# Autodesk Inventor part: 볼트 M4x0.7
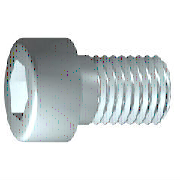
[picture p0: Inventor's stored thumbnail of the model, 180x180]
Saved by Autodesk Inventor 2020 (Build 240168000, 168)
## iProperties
IsCustomPart: 1
Created: 2015-10
Part Number: 볼트 M4x0.7
Material: 스테인리스강
Description: 6각머리 태핑 나사
Document SubType Name: Modeling
Standard: KS B 1003
Designer: mdu
Standards Organization: KS
Language: ko-KR
Size Designation: M 4 x 16
Categories: <MemberInstance><Categories><Category DisplayName="조임쇠" InternalName="e4da775c-781d-43d5-af7c-5136215cf5a6" Mnemonic="FSTN"><Category DisplayName="볼트" InternalN
Density: 8.08 g/cm^3
Mass: 2.70334 g
Surface Area: 3.81118 cm^2
Volume: 0.334572 cm^3
Appearance: 반광택
Author: mdu
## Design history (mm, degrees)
sketch "스케치1"
  geometry: L1 (-1, 0)-(14, 0); L2 (14, 0)-(14, 2); L3 (14, 2)-(1.75, 2); L4 (1.75, 2)-(1.32, 2); L5 (1.32, 2)-(0, 2); L6 (0, 2)-(0, 3.5); L7 (0, 3.5)-(-4, 3.5); L8 (-4, 3.5)-(-4, 1.732); L9 (-4, 1.732)-(-2, 1.732); L10 (-2, 1.732)-(-1, 0); L11 (-7.6, 0)-(17.6, 0) reference; L12 (0, -0.7)-(0, 4.2) reference; L13 (1.75, 2)-(0, 2)
  constraints: 22 end point, 6 parallel, 2 collinear, 2 perpendicular, 1 horizontal, 1 point on line
  dimensions: "d1" = 12.25 distance from line of L3.end L2 (= GEL); "d2" = 0.42952 distance of L4.end L3.end (computed from GAL); "d3" = 4 distance between parallel lines of L8 L6 (= KOH); "d4" = 2 distance of L8.end L9.end (= INTI); "d5" = 60 deg angle of L10 L1; "d6" = 4 diameter of L3 L1 (= GD); "d7" = 4 diameter of L5 L1 (= BDM); "d8" = 3.4641 diameter of L9 L1 (= 1.1547 x SW); "d9" = 7 diameter of L7 L1 (= KOD); "d26" = 14 distance between parallel lines of L12 L2 (= NLG)
revolve "본체" sketch "스케치1" stored, may be unused: angle "d10" = 90 deg
sketch "스케치2"
  geometry: L1 (0, -4.9)-(0, 4.9) reference; L2 (-4.9, 0)-(4.9, 0) reference; L3 (1.732, 0)-(0.866, -1.5); L4 (0.866, -1.5)-(-0.866, -1.5); L5 (-0.866, -1.5)-(-1.732, 0); L6 (-1.732, 0)-(-0.866, 1.5); L7 (-0.866, 1.5)-(0.866, 1.5); L8 (0.866, 1.5)-(1.732, 0); 2 further points
  constraints: 12 end point, 1 coincident, 1 horizontal alignment, 1 point on line, 12 other
extrude "슬롯" join sketch "스케치2" stored distance "d11" = 10; taper "d12" = 0 deg
workplane "Work Plane1"
fillet "Fillet2" dims "d30" = 0.1 (= R)
body "Solid1"
fillet "모깎기1" dims "d17" = 0.4 (= RR)
feature "스레드" dims "d13" = 12.25 (= GEL), "d14" = 0
chamfer "모따기1" distance "d15" = 0.42941 (= -0.5 x SPD + 0.5 x GD); stored, may be unused: second distance "d16" = 0.42941 (= GUL), angle "d27" = 45 deg
other parameters: "GD" = 4 (= NND) [user parameter; used in 2 equation terms], "NLG" = 14 [user parameter; used in 1 equation term], "GEL" = 12.25 [user parameter; used in 2 equation terms], "KOD" = 7 [user parameter; used in 1 equation term], "KOH" = 4 [user parameter; used in 1 equation term], "INTI" = 2 [user parameter; used in 1 equation term], "GAL" = 0.42941 (= 0.61345 x PTC) [user parameter; used in 1 equation term], "GUL" = 0.42941 (= 0.61345 x PTC) [user parameter; used in 1 equation term], "BDM" = 4 (= NND) [user parameter; used in 1 equation term], "SW" = 3 [user parameter; used in 2 equation terms], "RR" = 0.4 [user parameter; used in 1 equation term], "SPD" = 3.14117 (= NND - 1.2269 x PTC) [user parameter; used in 1 equation term], "d19" = 0, "d28" = 0, "d29" = 0, "R" = 0.1 [user parameter; used in 1 equation term], "PHH" = 0.2 [user parameter], "GD1" = 3.14117 (= THREADDIA - 1.2269 x PTC) [user parameter], "THREADDIA" = 4 [user parameter; used in 1 equation term], "FAWI" = 45 deg [user parameter], "TPU" = 14.28571 (computed from PTC) [user parameter], "PTC" = 0.7 [user parameter; used in 5 equation terms], "NND" = 4 [user parameter; used in 3 equation terms], "TOA" = 30 deg [user parameter], "E0" = 3.465 (= 1.155 x SW) [user parameter]
